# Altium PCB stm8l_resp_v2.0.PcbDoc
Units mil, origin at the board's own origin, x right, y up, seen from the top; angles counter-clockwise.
Board outline 2000 x 1200 mil, 2 copper layers (Top Layer, Bottom Layer); 68 components, 55 nets, 225 pads, 50 vias.
Unrouted connection lines stored in the file: 2.
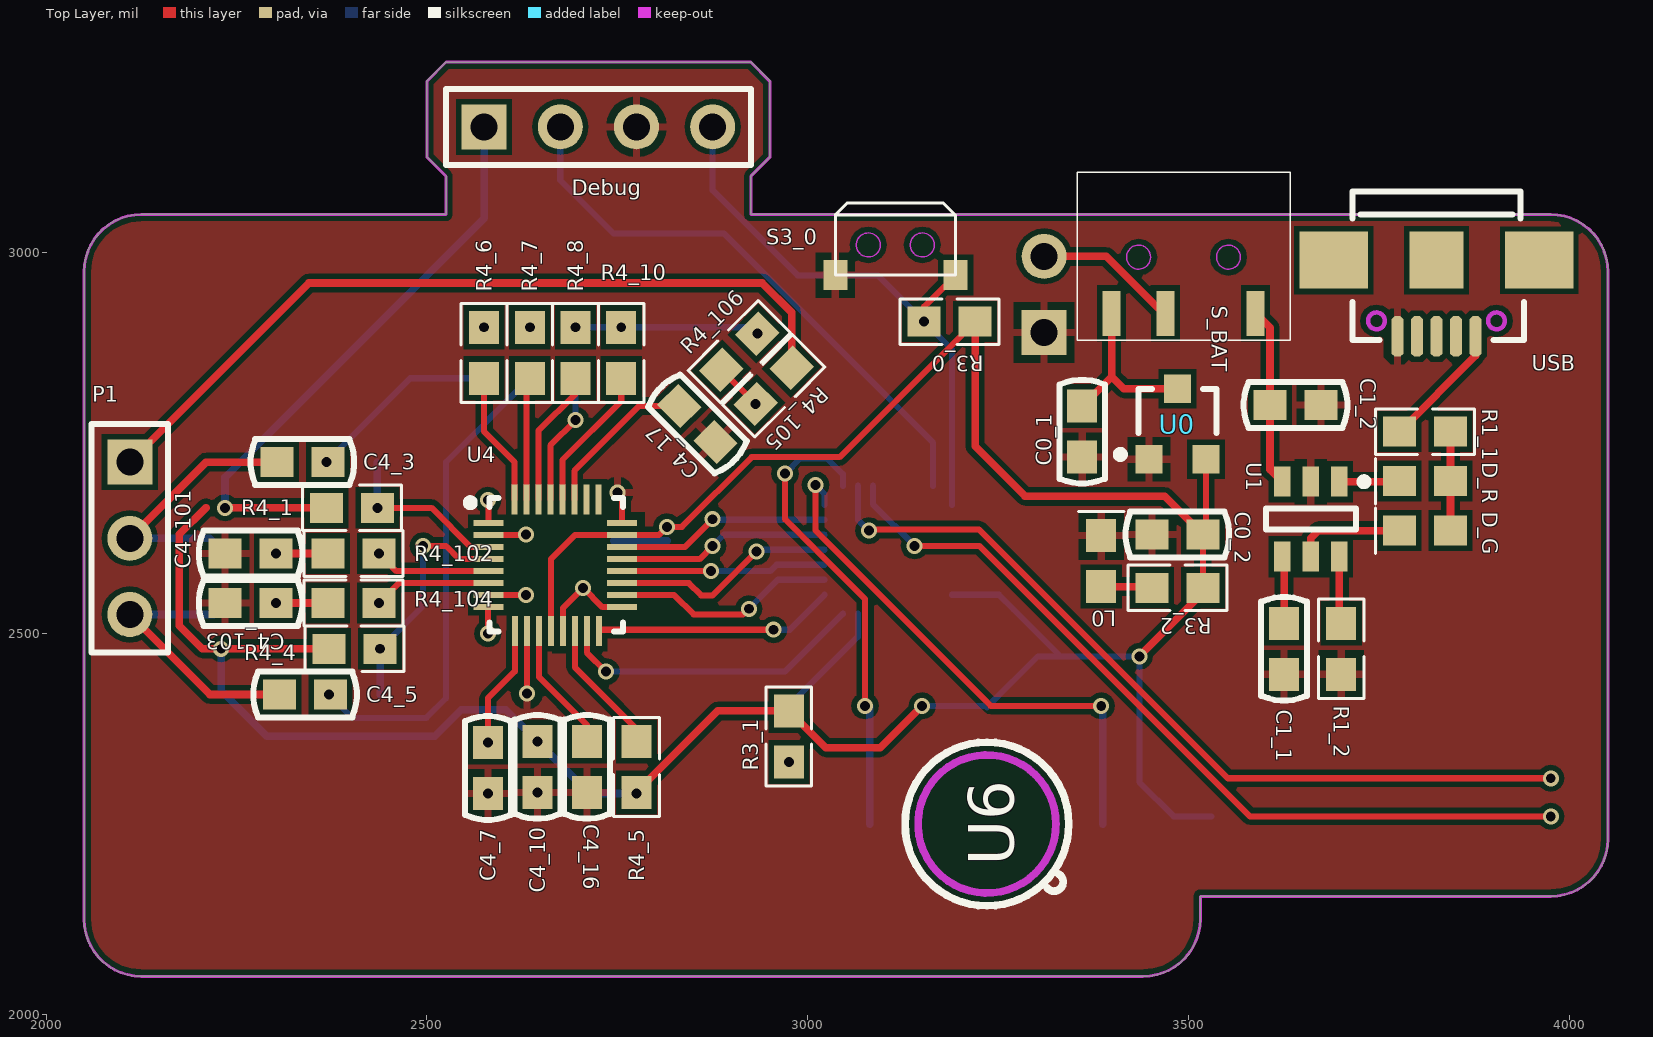
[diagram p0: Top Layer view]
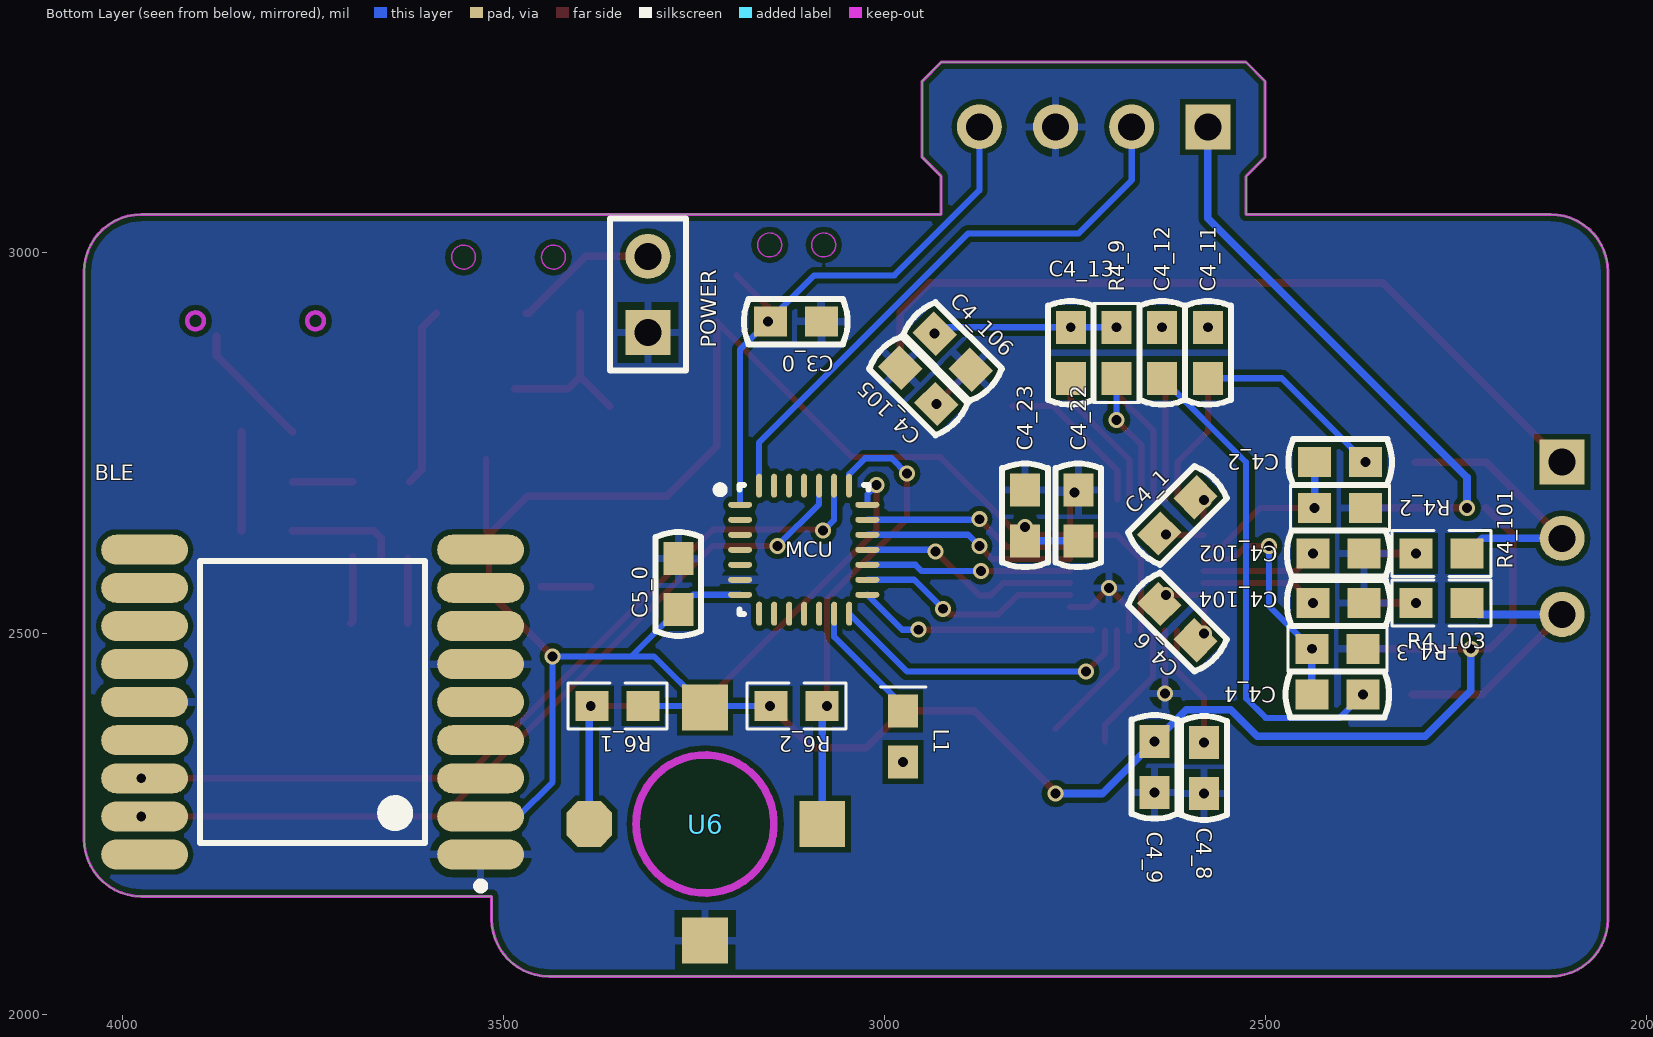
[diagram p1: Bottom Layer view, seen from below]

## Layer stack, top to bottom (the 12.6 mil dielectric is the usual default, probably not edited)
Top Layer: signal copper 1.4
Dielectric: dielectric 12.6, FR-4, Dk 4.8
Bottom Layer: signal copper 1.4

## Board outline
2125,2050 cw(c2125,2125) 2050,2125 2050,2975 cw(c2125,2975) 2125,3050 2525,3050 2525,3100 2500,3125 2500,3225 2525,3250 2925,3250 2950,3225 2950,3125 2925,3100 2925,3050 3975,3050 cw(c3975,2975) 4050,2975 4050,2230 cw(c3975,2230) 3975,2155 3515,2155 3515,2125 cw(c3440,2125) 3440,2050

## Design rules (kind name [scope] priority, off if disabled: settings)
Clearance Clearance_1 [ispad vs ispad] p1: gap=4
Clearance [All] p2: gap=7
PolygonConnect [All] p1: connectstyle=Relief reliefconductorwidth=10 reliefentries=4 polygonreliefangle="90 Angle" airgapwidth=10
RoutingVias [All] p1: holewidth=28 width=50 viastyle="Through Hole" minholewidth=28 minwidth=50 maxholewidth=28 maxwidth=50
SolderMaskExpansion [All] p1: expansion=4
Width [All] p1: maxlimit=10 minlimit=8 preferedwidth=10
28 further rules are at their usual default settings.

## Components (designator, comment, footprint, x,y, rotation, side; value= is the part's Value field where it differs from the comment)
BLE "BM-S02" BM-S02 3750,2410 r0 bottom
C0_1 "Cap" C-RAD-0603 3360,2765 r90 top
C0_2 "Cap" C-RAD-0603 3485,2630 r0 top
C1_1 "Cap" C-RAD-0603 3625,2480 r90 top
C1_2 "Cap" C-RAD-0603 3640,2800 r0 top
C3_0 "Cap" C-RAD-0603 3115.94,2909.37 r0 bottom
C4_1 "Cap" C-RAD-0603 2615,2655 r135 bottom
C4_2 "Cap" C-RAD-0603 2401.54,2725 r0 bottom
C4_3 "Cap" C-RAD-0603 2336.54,2725 r0 top
C4_4 "Cap" C-RAD-0603 2405,2420 r0 bottom
C4_5 "Cap" C-RAD-0603 2340,2420 r0 top
C4_6 "Cap" C-RAD-0603 2615,2515 r225 bottom
C4_7 "Cap" C-RAD-0603 2580,2323.46 r90 top
C4_8 "Cap" C-RAD-0603 2580,2323.46 r270 bottom
C4_9 "Cap" C-RAD-0603 2645,2325 r270 bottom
C4_10 "Cap" C-RAD-0603 2645,2325 r270 top
C4_11 "Cap" C-RAD-0603 2575,2868.46 r90 bottom
C4_12 "Cap" C-RAD-0603 2635,2868.46 r90 bottom
C4_13 "Cap" C-RAD-0603 2755,2868.46 r270 bottom
C4_16 "Cap" C-RAD-0603 2710,2325 r270 top
C4_17 "Cap" C-RAD-0603 2855,2775 r315 top
C4_22 "Cap" C-RAD-0603 2745,2655 r270 bottom
C4_23 "Cap" C-RAD-0603 2815,2655 r270 bottom
C4_101 "Cap" C-RAD-0603 2268.46,2605 r180 top
C4_102 "Cap" C-RAD-0603 2403.46,2605 r180 bottom
C4_103 "Cap" C-RAD-0603 2268.46,2540 r180 top
C4_104 "Cap" C-RAD-0603 2403.46,2540 r180 bottom
C4_105 "Cap" C-RAD-0603 2955,2825 r45 bottom
C4_106 "Cap" C-RAD-0603 2910,2870 r225 bottom
C5_0 "Cap" C-RAD-0603 3270,2565 r90 bottom
D_G "LED0" 0603-LED 3810,2635 r180 top
D_R "LED0" 0603-LED 3810,2700 r180 top
Debug "Header 4" HDR4X1_A 2575,3165 r0 top
L0 "LED" 0603-LED 3385,2595 r90 top
L1 "LED" 0603-LED 2975,2365 r90 bottom
MCU "STM8L151G" STM8L-QFN28 3105,2610 r180 bottom
P1 "Header 3" HDR3X1_A 2110,2725 r270 top
POWER "Header 2" HDR1X2 3310,2895 r90 bottom
R1_1 "Res1" 0603-1 3810,2765 r180 top
R1_2 "Res1" 0603-1 3700,2480 r270 top
R3_0 "Res1" 0603-1 3185.94,2909.37 r180 top
R3_1 "Res1" 0603-1 2975,2365 r270 top
R3_2 "Res1" 0603-1 3485,2560 r180 top
R4_1 "Res1" 0603-1 2401.54,2665 r0 top
R4_2 "Res1" 0603-1 2401.54,2665 r0 bottom
R4_3 "Res1" 0603-1 2405,2480 r180 bottom
R4_4 "Res1" 0603-1 2405,2480 r180 top
R4_5 "Res1" 0603-1 2775,2325 r90 top
R4_6 "Res1" 0603-1 2575,2868.46 r90 top
R4_7 "Res1" 0603-1 2635,2868.46 r270 top
R4_8 "Res1" 0603-1 2695,2868.46 r270 top
R4_9 "Res1" 0603-1 2695,2868.46 r90 bottom
R4_10 "Res1" 0603-1 2755,2868.46 r90 top
R4_101 "Res1" 0603-1 2268.46,2605 r0 bottom
R4_102 "Res1" 0603-1 2403.46,2605 r0 top
R4_103 "Res1" 0603-1 2268.46,2540 r0 bottom
R4_104 "Res1" 0603-1 2403.46,2540 r0 top
R4_105 "Res1" 0603-1 2955,2825 r225 top
R4_106 "Res1" 0603-1 2910,2870 r45 top
R6_1 "Res1" 0603-1 3350,2405 r180 bottom
R6_2 "Res1" 0603-1 3115,2405 r0 bottom
S3_0 "SW-PB" SW_PB2_2*4 3035.94,3049.37 r0 top
S_BAT "SW-SPDT" SWITCH_1P2T 3625,2940 r180 top
U0 "MCP1700" SOT-23 3485,2775 r0 top
U1 "TP4057" TP4057 3660,2650 r270 top
U4 "ADS1292R" ADS1292R-QFN-32 2670,2590 r0 top
U6 "MLX90615" MLX90615-2 3235,2250 r90 top
USB "USB_M" USB_MICRO 3825,2990 r180 top

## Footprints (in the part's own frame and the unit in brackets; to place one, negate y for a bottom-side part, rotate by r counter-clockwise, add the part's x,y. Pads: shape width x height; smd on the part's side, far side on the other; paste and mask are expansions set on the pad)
0603-1 [mm] "贴片带丝印"
  rect 1.1x1 smd: 1(-0.85,0) 2(0.85,0)
  silkscreen extent -1.65,-0.76 1.65,0.76, body extent -1.14,-0.38 1.14,0.38, height 1
0603-LED [mm]
  rect 1.1x1 smd: 1(-0.85,0) 2(0.85,0)
  silkscreen extent 1.65,-0.76 1.65,0.76, body extent -1.14,-0.38 1.14,0.38, height 1
ADS1292R-QFN-32 [mm] "QFN, 32-Leads, Body 4.00x4.00mm, Pitch 0.40mm, Thermal Pad 2.80x2.80mm, IPC Medium Density"
  rect 1x0.2 smd: 1(-2.261,1.397) 2(-2.261,0.997) 3(-2.261,0.597) 4(-2.261,0.197) 5(-2.261,-0.203) 6(-2.261,-0.603) 7(-2.261,-1.003) 8(-2.261,-1.403) 17(2.184,-1.403) 18(2.184,-1.003) 19(2.184,-0.603) 20(2.184,-0.203) 21(2.184,0.197) 22(2.184,0.597) 23(2.184,0.997) 24(2.184,1.397)
  rect 0.2x1 smd: 9(-1.385,-2.195) 10(-0.985,-2.195) 11(-0.585,-2.195) 12(-0.185,-2.195) 13(0.215,-2.195) 14(0.615,-2.195) 15(1.015,-2.195) 16(1.415,-2.195) 25(1.397,2.184) 26(0.997,2.184) 27(0.597,2.184) 28(0.197,2.184) 29(-0.203,2.184) 30(-0.603,2.184) 31(-1.003,2.184) 32(-1.403,2.184)
  silkscreen extent -3,-2.22 2.22,2.23, body extent -2.08,-2.04 2.07,2.11, height 1
BM-S02 [mm] "TQFP, 18-Leads, Body 11.20x15.10mm, Pitch 1.27mm, IPC Medium Density"
  oval 2.9x1 smd: 1(-5.6,5.08) 2(-5.6,3.81) 3(-5.6,2.54) 4(-5.6,1.27) 5(-5.6,0) 6(-5.6,-1.27) 7(-5.6,-2.54) 8(-5.6,-3.81) 9(-5.6,-5.08) 10(5.6,-5.08) 11(5.6,-3.81) 12(5.6,-2.54) 13(5.6,-1.27) 14(5.6,0) 15(5.6,1.27) 16(5.6,2.54) 17(5.6,3.81) 18(5.6,5.08)
  silkscreen extent -5.72,-4.7 3.75,6.25, body extent -5.6,-6.03 5.6,9.07, height 1.2
C-RAD-0603 [mm] "贴片电容"
  rect 1.1x1 smd: 1(-0.85,0) 2(0.85,0)
  silkscreen extent -1.73,-0.76 1.73,0.76, body extent -1.14,-0.38 1.14,0.38, height 1
HDR1X2 [mm] "Connector; Header; 2 Position"
  rect 1.5x1.5 hole 0.9: 1(0,0)
  round 1.5 hole 0.9: 2(2.54,0)
  silkscreen extent -1.27,-1.27 3.81,1.27
HDR3X1_A [mm] "Connector; Header; 3 Position"
  rect 1.5x1.5 hole 0.9: 1(0,0)
  round 1.5 hole 0.9: 2(2.54,0) 3(5.08,0)
  silkscreen extent -1.27,-1.27 6.35,1.27
HDR4X1_A [mm] "Connector; Header; 4 Position"
  rect 1.5x1.5 hole 0.9: 1(0,0)
  round 1.5 hole 0.9: 2(2.54,0) 3(5.08,0) 4(7.62,0)
  silkscreen extent -1.27,-1.27 8.89,1.27
MLX90615-2 [mil] "红外体温传感器"
  oct 60x60 smd far side: 1(0,-152)
  rect 60x60 smd far side: 2(153,0) 3(0,154) 4(-153,0)
  Keep-Out Layer circle w10: c0,0 r90.55
  silkscreen extent -107,-107 107,107
SOT-23 [mm]
  rect 0.9x0.95 smd: 1(-0.95,-1.175) 2(0.95,-1.175) 3(0,1.175)
  silkscreen extent -2.03,-1.14 1.3,1.18
STM8L-QFN28 [mm] "QFN, 28-Leads, Body 4.00x4.00mm, Pitch 0.50mm, Thermal Pad 3.30x3.30mm, IPC Medium Density"
  oval 0.8x0.2 smd: 1(-2.134,1.499) 2(-2.134,0.999) 3(-2.134,0.499) 4(-2.134,-0.001) 5(-2.134,-0.501) 6(-2.134,-1.001) 7(-2.134,-1.501) 15(2.108,-1.501) 16(2.108,-1.001) 17(2.108,-0.501) 18(2.108,-0.001) 19(2.108,0.499) 20(2.108,0.999) 21(2.108,1.499)
  oval 0.2x0.8 smd: 8(-1.499,-2.134) 9(-0.999,-2.134) 10(-0.499,-2.134) 11(0.001,-2.134) 12(0.501,-2.134) 13(1.001,-2.134) 14(1.501,-2.134) 22(1.499,2.134) 23(0.999,2.134) 24(0.499,2.134) 25(-0.001,2.134) 26(-0.501,2.134) 27(-1.001,2.134) 28(-1.501,2.134)
  silkscreen extent -2.93,-2.15 2.15,2.15, body extent -2.01,-2 1.99,2, height 0.75
SW_PB2_2*4 [mm] "2*4"
  rect 0.8x1 smd: 1(0,-2.007) 2(4.013,-2.007)
  Keep-Out Layer circle w0.051: c1.1,-1 r0.4
  Keep-Out Layer circle w0.051: c2.9,-1 r0.4
  silkscreen extent 0,-2 4,0.41
SWITCH_1P2T [mm]
  rect 0.6x1.5 smd: 1(0.95,0.5) 2(3.95,0.5) 3(5.75,0.5)
  Keep-Out Layer circle w0.051: c1.854,-1.372 r0.4
  Keep-Out Layer circle w0.051: c4.851,-1.372 r0.4
  silkscreen extent -0.2,-4.2 6.9,1.4, body extent 0,-4.17 6.68,0, height 1.4
TP4057 [mm] "SOT23, 6-Leads, Body 2.90x2.90mm, Pitch 0.95mm, IPC Medium Density"
  rect 1x0.55 smd: 1(-1.25,0.95) 2(-1.25,0) 3(-1.25,-0.95) 4(1.25,-0.95) 5(1.25,0) 6(1.25,0.95)
  silkscreen extent -1.37,-1.5 0.35,1.9, body extent -0.85,-1.5 0.85,1.5, height 1.1
USB_MICRO [mm] "USB方孔"
  oct 0.4x1.35 smd: 1(-1.3,2.54) 2(-0.65,2.54) 3(0,2.54) 4(0.65,2.54) 5(1.3,2.54)
  rect 2.286x1.9 smd: 6(3.429,0) 7(-3.429,0)
  rect 1.8x1.9 smd: 8(0,0)
  Keep-Out Layer circle w0.15: c2,2.023 r0.28
  Keep-Out Layer circle w0.15: c-2,2.023 r0.28
  silkscreen extent -2.92,-2.29 2.79,2.67

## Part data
BLE: "蓝牙4.0模块"
C0_1 C0_2 C1_1 C1_2 C3_0 C4_1 C4_2 C4_3 C4_4 C4_5 C4_6 C4_7 C4_8 C4_9 C4_10 C4_11 C4_12 C4_13 C4_16 C4_17 C4_22 C4_23 C4_101 C4_102 C4_103 C4_104 C4_105 C4_106 C5_0: "无极性电容"
D_G D_R: "发光二极管"
Debug P1: "接插件"
MCU: "STM8L单片机28引脚"
POWER: "Header, 2-Pin"
R1_1 R1_2 R3_0 R3_1 R3_2 R4_1 R4_2 R4_3 R4_4 R4_5 R4_6 R4_7 R4_8 R4_9 R4_10 R4_101 R4_102 R4_103 R4_104 R4_105 R4_106 R6_1 R6_2: "贴片电阻"
S3_0: "微动开关"
S_BAT: "开关"
U0: "微型稳压芯片"
U1: "锂电池充电管理"
U4: "集成呼吸阻抗 ECG 前端"
U6: "红外体温传感器"
USB: "MicroUSB接口"

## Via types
v1: diameter 21, hole 13, Top Layer to Bottom Layer, 50 vias

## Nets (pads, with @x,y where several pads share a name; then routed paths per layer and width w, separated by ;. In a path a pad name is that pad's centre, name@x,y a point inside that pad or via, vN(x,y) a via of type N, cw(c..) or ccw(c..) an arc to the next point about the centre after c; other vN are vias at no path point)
1N2N: C4_102.1 R4_102.2 U4.5 | length 153.6
  Top Layer w8: v1(2436.93,2605) 2459.93,2582 U4.5
1N2P: C4_104.1 R4_104.2 U4.6 | length 154.9
  Top Layer w8: v1(2436.93,2540) 2463.18,2566.25 U4.6
3.3V: BLE.2 C0_2.2 C4_9.1 C4_10.1 C4_22.2 C4_23.2 C5_0.1 Debug.1 MCU.7 R3_0.1 R3_1.1 R3_2.1 R4_1.1 R4_4.2 R4_5.1 R6_1.2 R6_2.2 U0.2 U4.12 U4.23 U6.2 | length 4805
  Top Layer w8: U4.12 2662.71,2597.71 2694.25,2629.25 U4.23 2804.25,2629.25 v1(2815,2640) 2834.59,2640 2926.09,2731.5 3041.54,2731.5 R3_0.1 ; R3_2.1 C0_2.2 3522.4,2633.94 U0.2
  Top Layer w10: 2210,2665 2175,2630 2175,2510 2205,2480 v1(2230,2480) R4_4.2 ; v1(2235,2665) R4_1.1 ; R4_5.1 2881.93,2398.46 R3_1.1 3023.46,2350 3095,2350 v1(3150,2405) ; R3_0.1 3219.41,2745.59 3285,2680 3468.46,2680 C0_2.2 ; v1(3435,2470) 3518.46,2553.46 R3_2.1
  Bottom Layer w8: R6_2.2 U6.2@3237,2405 ; MCU.7 3250.65,2550.89 C5_0.1 3331.54,2470 ; U6.2 U6.2@3237,2405 ; R6_1.2 U6.2@3237,2405 ; BLE.2 3480,2260 3435,2305 v1(3435,2470) 3331.54,2470 ; U6.2@3237,2405 3302,2470 3331.54,2470
  Bottom Layer w10: v1(2230,2480) 2230,2425 2290,2365 2510,2365 2545,2400 2603.46,2400 v1(2645,2358.46) 2713.46,2290 v1(2775,2290) ; v1(2235,2665) 2235,2705 2575,3045 Debug.1 ; C4_22.2 C4_23.2
5V: R1_1.2 USB.1 | length 166.3
  Top Layer w10: R1_1.2 3876.18,2864.65 USB.1
GND: BLE.1 BLE.6 BLE.14 C0_1.1 C0_2.1 C1_1.1 C1_2.2 C3_0.1 C4_7.1 C4_8.2 C4_9.2 C4_10.2 C4_16.2 C4_17.2 C4_22.1 C4_23.1 C4_101.2 C4_102.2 C4_103.2 C4_104.2 C4_105.2 C4_106.2 C5_0.2 Debug.3 L0.2 MCU.6 POWER.1 R1_2.2 R4_2.1 R4_3.2 S3_0.1 U0.1 U1.2 U4.10 U4.13 U4.17 U4.24 U6.4 USB.5 | length 253.7
  Top Layer w8: v1(2631.21,2421.21) U4.10 ; U4.13 2678.46,2533.46 v1(2705,2560) 2730.24,2534.76 U4.17 ; v1(2750,2685) 2756,2679 U4.24
  other v1: 2580,2290 2645,2291.54
IIC_SCL: MCU.22 R6_2.1 U6.3 | length 610.9
  Top Layer w8: v1(2970,2710) 2970,2650 3075,2545 v1(3075,2405)
  Bottom Layer w8: v1(2970,2710) 2990,2730 3025,2730 3046,2709 MCU.22
  Bottom Layer w10: U6.3 R6_2.1@3081,2404.46
IIC_SDA: MCU.21 R6_1.1 U6.1 | length 712.7
  Top Layer w8: v1(3010,2695) 3010,2635 3240,2405 v1(3385,2405)
  Bottom Layer w8: v1(3010,2695) 3022,2683 MCU.21
  Bottom Layer w10: U6.1 R6_1.1@3387,2401.46
LA: C4_5.1 P1.3 R4_103.1 | length 371.2
  Top Layer w10: P1.3 2215,2420 C4_5.1
  Bottom Layer w10: P1.3 2220,2525 R4_103.1
LED0: L1.2 MCU.13 | length 158.5
  Bottom Layer w8: L1.2@2975,2405 3065.57,2495.57 MCU.13
NetC1_1_2: C1_1.2 U1.4 | length 84.9
  Top Layer w10: C1_1.2 U1.4@3625,2598.39
NetC4_1_1: C4_1.1 U4.2 | length 48.2
  Top Layer w8: U4.2 v1@2629.24,2629.24
  other v1: 2630,2630
NetC4_1_2: C4_1.2 U4.1 | length 29
  Top Layer w8: U4.1 v1@2581,2674
  other v1: 2580,2675
NetC4_2_1: C4_2.1 C4_3.2 C4_11.1 | length 252.5
  Bottom Layer w8: v1(2368.07,2725) 2478.07,2835 C4_11.1
NetC4_2_2: C4_2.2 R4_1.2 R4_2.2 U4.3 | length 227.3
  Top Layer w8: v1(2435,2665) 2506.07,2665 2557.57,2613.5 U4.3
  Bottom Layer w10: v1(2435,2665) C4_2.2
NetC4_4_1: C4_4.1 C4_5.2 C4_12.1 | length 642.4
  Bottom Layer w8: v1(2371.54,2420) 2402.22,2389.31 2499.31,2389.31 2525,2415 2525,2725 C4_12.1
NetC4_4_2: C4_4.2 R4_3.1 R4_4.1 U4.4 | length 311.6
  Top Layer w8: v1(2495,2615) 2525,2615 2542.25,2597.75 U4.4
  Bottom Layer w8: v1(2438.46,2480) 2495,2536.54 v1(2495,2615)
  Bottom Layer w10: C4_4.2 v1(2438.46,2480)
NetC4_6_1: C4_6.1 U4.7 | length 49
  Top Layer w8: U4.7 v1(2630,2550.5)
NetC4_6_2: C4_6.2 U4.8 | length 43.8
  Top Layer w8: v1@2580,2510 v1(2580,2500) U4.8@2580,2533.76
NetC4_7_2: C4_7.2 C4_8.1 U4.9 | length 161.4
  Top Layer w8: v1(2580,2356.93) 2580,2415 2615.46,2450.46 U4.9
NetC4_11_2: C4_11.2 R4_6.2
  other v1: 2575,2901.93
NetC4_12_2: C4_12.2 R4_7.1
  other v1: 2635,2901.93
NetC4_13_2: C4_13.2 R4_10.1 U4.28 | length 191
  Top Layer w8: U4.28 2677.75,2727.75 2755,2805 R4_10.1
NetC4_101_1: C4_101.1 R4_101.2 R4_102.1 | length 68.1
  Top Layer w10: v1(2301.93,2605) R4_102.1
NetC4_103_1: C4_103.1 R4_103.2 R4_104.1 | length 68.1
  Top Layer w10: v1(2301.93,2540) R4_104.1
NetC4_105_1: C4_105.1 R4_105.2 R4_106.1 | length 63.6
  Top Layer w8: R4_106.1 v1(2931.34,2801.34)
NetD_G_1: D_G.1 D_R.1 R1_1.1 | length 130
  Top Layer w10: D_G.1 D_R.1 R1_1.1
NetD_G_2: D_G.2 U1.5 | length 144.9
  Top Layer w10: U1.5 3660,2625 3670,2635 D_G.2
NetD_R_2: D_R.2 U1.1 | length 78.3
  Top Layer w10: U1.1 D_R.2@3775.75,2699.21
NetL0_1: L0.1 R3_2.2 | length 65
  Top Layer w10: L0.1 R3_2.2@3450,2561.54
NetL1_1: L1.1 R3_1.2
  other v1: 2975,2331.54
NetPOWER_2: POWER.2 S_BAT.2 | length 190.4
  Top Layer w10: POWER.2 3391.55,2995 3466.23,2920.32 S_BAT.2
NetR1_2_1: R1_2.1 U1.6 | length 88.4
  Top Layer w10: U1.6 3697.4,2516.06 R1_2.1
NetR4_5_2: R4_5.2 U4.14 | length 162.1
  Top Layer w8: U4.14 2694.2,2455.8 R4_5.2@2775,2375
NetR4_6_1: R4_6.1 U4.32 | length 175.5
  Top Layer w8: R4_6.1 2575,2765 2614.76,2725.24 U4.32
NetR4_7_2: R4_7.2 U4.31 | length 154.5
  Top Layer w8: U4.31 R4_7.2@2630.5,2830.5
NetR4_8_2: R4_8.2 U4.30 | length 179.2
  Top Layer w8: U4.30 2646.25,2766.25 2695,2815 R4_8.2
NetR4_9_1: R4_9.1 U4.29 | length 172.7
  Top Layer w8: U4.29 2662,2747 v1(2695,2780)
  Bottom Layer w8: v1(2695,2780) R4_9.1
NRST: C3_0.2 Debug.4 MCU.1 R3_0.2 S3_0.2 | length 765.9
  Top Layer w8: v1(3152.48,2909.37) 3152.48,2928.91 S3_0.2
  Bottom Layer w8: Debug.4 2875,3081.66 2986.66,2970 3091.85,2970 v1(3152.48,2909.37) 3189,2872.85 MCU.1
RA: C4_3.1 P1.2 R4_101.1 | length 367.8
  Top Layer w10: P1.2 2210,2725 C4_3.1
  Bottom Layer w10: P1.2 2215,2625 R4_101.1
READY: MCU.20 U4.22 | length 280.4
  Top Layer w8: U4.22 2838.5,2613.5 v1(2875,2650)
  Bottom Layer w8: v1@2875.69,2649.31 MCU.20
RESET: MCU.14 U4.15 | length 406.3
  Top Layer w8: U4.15 2709.95,2475.05 v1(2735,2450)
  Bottom Layer w8: v1(2735,2450) 2969.89,2450 MCU.14
RL: P1.1 R4_105.1 | length 1054.7
  Top Layer w10: P1.1 2345,2960 2940,2960 2978.66,2921.34 R4_105.1
RL-OUT: C4_13.1 C4_106.1 R4_8.1 R4_9.2 R4_10.2 R4_106.2 | length 242.1
  Bottom Layer w8: v1(2695,2901.93) v1(2755,2901.93) 2925.4,2901.93 v1(2933.66,2893.66)
RXD: BLE.16 MCU.23 | length 1095.8
  Top Layer w8: v1(3080,2635) 3081.5,2636.5 3224.71,2636.5 3551.21,2310 v1(3975,2310)
  Bottom Layer w8: MCU.23 3065.69,2649.31 v1(3080,2635)
SAT0: C0_1.2 S_BAT.3 U0.3 | length 230.8
  Top Layer w10: C0_1.2 3398.62,2837.09 ; S_BAT.3 3398.62,2837.09 ; U0.3 3414.45,2821.26 3398.62,2837.09
SAT1: C1_2.1 S_BAT.1 U1.3 | length 235.6
  Top Layer w10: S_BAT.1 3606.54,2901.38 C1_2.1 3606.54,2715.28 U1.3
SPI_CLK: MCU.17 U4.20 | length 269.4
  Top Layer w8: U4.20 v1(2872.99,2582.01)
  Bottom Layer w8: v1(2872.99,2582.01) 2950.79,2582.01 2959.05,2590.26 MCU.17
SPI_CS: MCU.16 U4.18 | length 295.4
  Top Layer w8: U4.18 2824.49,2550.51 2850,2525 2915,2525 v1(2922.5,2532.5)
  Bottom Layer w8: v1(2922.5,2532.5) 2960.57,2570.57 MCU.16
SPI_MISO: MCU.19 U4.21 | length 279.2
  Top Layer w8: U4.21 2857.76,2597.76 v1(2875,2615)
  Bottom Layer w8: v1(2875,2615) 2889.63,2629.63 MCU.19
SPI_MOSI: MCU.18 U4.19 | length 297.6
  Top Layer w8: U4.19 2843.74,2566.26 2860,2550 2875,2550 v1(2932.5,2607.5)
  Bottom Layer w8: v1(2932.5,2607.5) 2934.94,2609.94 MCU.18
START: MCU.15 U4.16 | length 313.9
  Top Layer w8: U4.16@2727.1,2505 v1(2955,2505)
  Bottom Layer w8: v1(2955,2505) 2976.11,2505 MCU.15
SWIM: Debug.2 MCU.28 | length 758.5
  Bottom Layer w8: Debug.2 2675,3095 2745,3025 2890,3025 3164.11,2750.89 MCU.28
TXD: BLE.17 MCU.24 | length 1083.7
  Top Layer w8: v1(3140,2615) 3225,2615 3580,2260 v1(3975,2260)
  Bottom Layer w8: MCU.24 3085.37,2669.63 v1(3140,2615)
VCAP1: C4_16.1 U4.11 | length 171.2
  Top Layer w8: U4.11 2646.96,2443.04 2710,2380 C4_16.1
VCAP2: C4_17.1 U4.27 | length 210.6
  Top Layer w8: U4.27 2693.5,2713.5 2778.66,2798.66 C4_17.1
pads on no net: BLE.3 BLE.4 BLE.5 BLE.7 BLE.8 BLE.9 BLE.10 BLE.11 BLE.12 BLE.13 BLE.15 BLE.18 MCU.2 MCU.3 MCU.4 MCU.5 MCU.8 MCU.9 MCU.10 MCU.11 MCU.12 MCU.25 MCU.26 MCU.27 U4.25 U4.26 USB.2 USB.3 USB.4 USB.6 USB.7 USB.8

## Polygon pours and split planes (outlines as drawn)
GND on Top Layer "Top Layer-No Net" (solid, remove dead copper, pour order 7): 2050,3250 4050,3250 4050,2050 2050,2050 2050,3250
GND on Bottom Layer "Top Layer-No Net" (solid, remove dead copper, pour order 9): 2050,3250 4050,3250 4050,2050 4045,2055 2050,2055 2050,3250

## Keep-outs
Keep-Out Layer:
  the board outline again, w3.94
